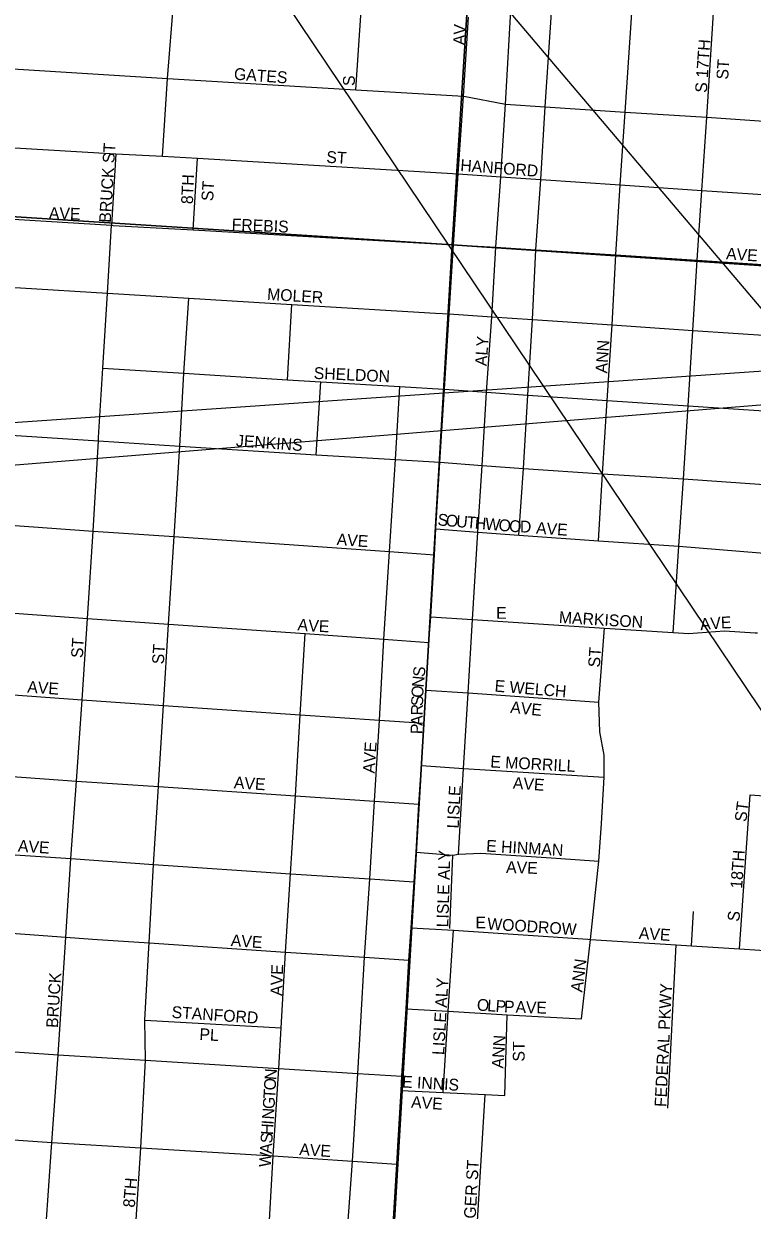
# Model space of a CAD drawing. Extents: x 0 to 34, y -6.2 to 22.
# Drawn here: x 7.214 to 7.798, y 15.431 to 16.383 of the extents above; entities that cross this region are included whole.
import ezdxf

# ---------------------------------------------------------------- set-up
doc = ezdxf.new("R2010")
doc.units = 0
for name, color, linetype in [('GM_X_City_Street', 7, 'Continuous'), ('GM_X_City_Street_Text', 7, 'Continuous'), ('GM_X_Corporation', 7, 'Continuous'), ('GM_X_Section', 7, 'Continuous'), ('SH_Data', 7, 'Continuous')]:
    doc.layers.add(name, color=color, linetype=linetype)

msp = doc.modelspace()

# ---------------------------------------------------------------- linework, layer by layer
at = {"layer": 'GM_X_City_Street'}
for points in [[(7.32508, 16.27676), (7.32919, 16.33906), (7.33421, 16.40232), (7.3364, 16.43316), (7.33992, 16.48027), (7.34271, 16.51996), (7.34542, 16.55929), (7.3485, 16.59888), (7.3519, 16.63865), (7.35476, 16.6813), (7.35765, 16.72304), (7.36053, 16.76297), (7.36453, 16.82192), (7.37158, 16.92099), (7.37633, 16.98634), (7.37905, 17.0267)], [(7.48036, 16.32986), (7.48466, 16.39349), (7.48699, 16.42288), (7.49064, 16.4691), (7.49371, 16.50912), (7.49674, 16.54846), (7.49957, 16.5877), (7.50258, 16.62725), (7.50564, 16.67008), (7.50871, 16.71187)], [(7.56258, 15.71668), (7.56656, 15.78555), (7.57032, 15.84609), (7.57386, 15.90499), (7.57829, 15.97507), (7.58172, 16.02856), (7.58521, 16.0873), (7.5894, 16.14776), (7.59258, 16.20355), (7.5967, 16.26005), (7.60038, 16.3184), (7.605, 16.39804), (7.6093, 16.4607), (7.61453, 16.53898)], [(7.61106, 15.9727), (7.6147, 16.02623), (7.61841, 16.08493), (7.62216, 16.14554), (7.62473, 16.20157), (7.62879, 16.25804), (7.63212, 16.31623), (7.63746, 16.396), (7.64133, 16.45859), (7.64678, 16.53671)], [(7.67496, 15.96812), (7.67822, 16.02195), (7.68186, 16.08073), (7.68587, 16.1413), (7.6889, 16.1974), (7.69243, 16.25376), (7.6964, 16.31198), (7.7017, 16.39152), (7.70564, 16.45429), (7.70723, 16.47221)], [(7.73492, 15.89456), (7.73958, 15.96384), (7.74334, 16.01793), (7.74708, 16.07645), (7.75068, 16.13694), (7.75424, 16.19312), (7.75796, 16.24906), (7.7619, 16.30801), (7.76695, 16.38727), (7.77087, 16.4499)], [(7.50892, 15.3982), (7.51307, 15.46819), (7.51391, 15.48255), (7.51655, 15.52729), (7.51727, 15.5388), (7.52053, 15.59278), (7.52292, 15.63183), (7.52454, 15.65774), (7.52697, 15.6946), (7.52856, 15.71838), (7.53091, 15.75694), (7.53286, 15.78789), (7.53508, 15.82183), (7.53654, 15.84839), (7.53887, 15.88668), (7.54041, 15.90725), (7.54328, 15.957), (7.54453, 15.97769), (7.5478, 16.03115), (7.55148, 16.08967), (7.55512, 16.15009), (7.5586, 16.20564), (7.56239, 16.26247), (7.56659, 16.3249), (7.57064, 16.38816)], [(7.07741, 16.35438), (7.17913, 16.34842), (7.32919, 16.33906), (7.48036, 16.32986), (7.56659, 16.3249), (7.56704, 16.32482)], [(7.56704, 16.32482), (7.60038, 16.3184), (7.63212, 16.31623), (7.6964, 16.31198), (7.7619, 16.30801), (7.82705, 16.30342), (7.91771, 16.29734), (7.99602, 16.29229), (8.02051, 16.29083)], [(6.89845, 16.30244), (6.94232, 16.29983), (6.9475, 16.29952), (6.97739, 16.29774), (7.07087, 16.29179), (7.08667, 16.29088), (7.17478, 16.28531), (7.28777, 16.2785), (7.32508, 16.27676), (7.35307, 16.27505), (7.56239, 16.26247)], [(7.28777, 16.2785), (7.28428, 16.22123), (7.28563, 16.22115)], [(7.34977, 16.21751), (7.35307, 16.27505)], [(7.56239, 16.26247), (7.5967, 16.26005), (7.62879, 16.25804), (7.69243, 16.25376), (7.75796, 16.24906), (7.82345, 16.24479), (7.91708, 16.23865), (7.99262, 16.23384), (8.01778, 16.23191)], [(6.97368, 16.24118), (7.08311, 16.23357), (7.28428, 16.22123)], [(7.27387, 16.05096), (7.27723, 16.10668), (7.28106, 16.16679), (7.28428, 16.22123)], [(7.28563, 16.22115), (7.34977, 16.21751), (7.46087, 16.21107), (7.46154, 16.21104)], [(7.46154, 16.21104), (7.5586, 16.20564), (7.55928, 16.20559)], [(7.55928, 16.20559), (7.59258, 16.20355), (7.62473, 16.20157), (7.6889, 16.1974), (7.75424, 16.19312), (7.8189, 16.18903), (7.88242, 16.18456), (7.91372, 16.18255), (7.98951, 16.17755), (8.07671, 16.17149), (8.14534, 16.16706)], [(7.15346, 16.17462), (7.21106, 16.17115), (7.28106, 16.16679), (7.34629, 16.16274), (7.42896, 16.15757), (7.54425, 16.15074)], [(7.32555, 15.8321), (7.3258, 15.83615), (7.32981, 15.90134), (7.33447, 15.97157), (7.3389, 16.04403), (7.34235, 16.10255), (7.34629, 16.16274)], [(7.42555, 16.09732), (7.42896, 16.15757)], [(7.54425, 16.15074), (7.55512, 16.15009), (7.5894, 16.14776), (7.62216, 16.14554), (7.68587, 16.1413), (7.75068, 16.13694), (7.8155, 16.13266), (7.87947, 16.12842), (7.94636, 16.12399)], [(7.27723, 16.10668), (7.34235, 16.10255), (7.42555, 16.09732), (7.45209, 16.09562), (7.5157, 16.09181), (7.5507, 16.08972)], [(7.44848, 16.03717), (7.45209, 16.09562)], [(7.48418, 15.5822), (7.48716, 15.63411), (7.49148, 15.69691), (7.49514, 15.75937), (7.49924, 15.82422), (7.50286, 15.88927), (7.50721, 15.95967), (7.51207, 16.03337), (7.5157, 16.09181)], [(7.5507, 16.08972), (7.55148, 16.08967), (7.58521, 16.0873), (7.61841, 16.08493), (7.68186, 16.08073), (7.74708, 16.07645), (7.81163, 16.07206), (7.87595, 16.06782), (7.94137, 16.06369)], [(6.90406, 16.07177), (6.93938, 16.06957), (6.96568, 16.06778), (7.00456, 16.06526), (7.07447, 16.06077), (7.13663, 16.05687), (7.20353, 16.05283), (7.27372, 16.04839), (7.3389, 16.04403), (7.44848, 16.03717), (7.51207, 16.03337), (7.5478, 16.03115), (7.58172, 16.02856), (7.6147, 16.02623), (7.67822, 16.02195), (7.74334, 16.01793), (7.80803, 16.01342), (7.87231, 16.0091), (7.93258, 16.00514)], [(7.22386, 15.29002), (7.22538, 15.31483), (7.22856, 15.36547), (7.23159, 15.41589), (7.23629, 15.48566), (7.24137, 15.55596), (7.2475, 15.65017), (7.25167, 15.71327), (7.25603, 15.77536), (7.26068, 15.84062), (7.26489, 15.90585), (7.26935, 15.97592), (7.27372, 16.04839), (7.27387, 16.05096)], [(7.06808, 15.9894), (7.07019, 15.98926), (7.19928, 15.98085), (7.26935, 15.97592), (7.33447, 15.97157), (7.50721, 15.95967), (7.54328, 15.957)], [(7.54453, 15.97769), (7.57829, 15.97507), (7.61106, 15.9727), (7.67496, 15.96812), (7.73958, 15.96384), (7.80485, 15.95861), (7.86883, 15.95433), (7.93546, 15.95041)], [(6.90834, 15.93074), (6.99731, 15.92399), (7.06587, 15.91941), (7.19508, 15.91077), (7.26489, 15.90585), (7.32981, 15.90134), (7.43951, 15.89384), (7.50286, 15.88927), (7.53887, 15.88668)], [(7.54041, 15.90725), (7.57386, 15.90499), (7.67974, 15.89804)], [(7.40989, 15.40452), (7.41398, 15.47475), (7.41856, 15.5449), (7.42034, 15.5774), (7.42379, 15.63819), (7.42779, 15.70103), (7.43178, 15.76365), (7.43572, 15.82856), (7.43951, 15.89384)], [(7.66146, 15.58475), (7.66868, 15.64846), (7.67539, 15.71125), (7.67742, 15.74127), (7.6795, 15.77854), (7.67957, 15.79608), (7.67615, 15.81501), (7.67519, 15.83884), (7.67974, 15.89804)], [(7.67974, 15.89804), (7.73492, 15.89456), (7.74727, 15.89369), (7.77621, 15.896), (7.78843, 15.89516), (7.80064, 15.89433), (7.80264, 15.89421)], [(7.06188, 15.8546), (7.19061, 15.84555), (7.26068, 15.84062), (7.3258, 15.83615), (7.43572, 15.82856), (7.49924, 15.82422), (7.53508, 15.82183)], [(7.53654, 15.84839), (7.57032, 15.84609), (7.67519, 15.83884)], [(7.32184, 15.772), (7.32555, 15.8321)], [(6.91246, 15.79876), (6.95277, 15.79636), (6.98898, 15.79399), (7.02417, 15.79172), (7.05739, 15.78945), (7.18602, 15.78035), (7.25603, 15.77536), (7.32178, 15.77107), (7.43178, 15.76365), (7.49514, 15.75937), (7.53091, 15.75694)], [(7.53286, 15.78789), (7.56656, 15.78555), (7.6795, 15.77854)], [(7.31417, 15.64176), (7.3144, 15.64569), (7.31775, 15.70853), (7.32178, 15.77107), (7.32184, 15.772)], [(7.78826, 15.641), (7.79685, 15.76448)], [(7.79685, 15.76448), (7.85678, 15.76018), (7.92659, 15.7549)], [(7.05319, 15.72691), (7.18218, 15.71782), (7.25167, 15.71327), (7.31775, 15.70853), (7.42779, 15.70103), (7.49148, 15.69691), (7.52697, 15.6946)], [(7.52856, 15.71838), (7.55803, 15.71611), (7.56258, 15.71668), (7.58051, 15.71749), (7.64109, 15.71365), (7.67539, 15.71125)], [(7.55563, 15.65705), (7.55803, 15.71611)], [(7.03816, 15.66529), (7.04925, 15.66448), (7.09295, 15.6614), (7.12955, 15.65876), (7.17765, 15.65543), (7.1819, 15.65505), (7.2475, 15.65017), (7.26883, 15.64867), (7.3144, 15.64569), (7.42379, 15.63819), (7.48716, 15.63411), (7.52292, 15.63183)], [(7.74968, 15.64338), (7.7512, 15.67083)], [(7.52454, 15.65774), (7.55858, 15.65588), (7.66654, 15.6486)], [(7.55417, 15.58577), (7.55449, 15.59079), (7.55858, 15.65588)], [(7.66654, 15.6486), (7.66868, 15.64846), (7.73741, 15.64414), (7.74968, 15.64338), (7.78826, 15.641)], [(7.31138, 15.55154), (7.31138, 15.55161), (7.31086, 15.58363), (7.31417, 15.64176)], [(7.7307, 15.51295), (7.73741, 15.64414)], [(7.78826, 15.641), (7.9186, 15.63221), (8.1509, 15.61549), (8.18538, 15.61304)], [(7.52053, 15.59278), (7.55449, 15.59079), (7.60174, 15.58781), (7.66146, 15.58475)], [(7.31086, 15.58363), (7.42034, 15.5774)], [(7.47882, 15.49225), (7.48182, 15.541), (7.48418, 15.5822)], [(7.5504, 15.52568), (7.55417, 15.58577)], [(7.59992, 15.52312), (7.60174, 15.58781)], [(7.03952, 15.56918), (7.04242, 15.56899), (7.08648, 15.56592), (7.12337, 15.56372), (7.13288, 15.56319), (7.17602, 15.56039), (7.18292, 15.55994), (7.24137, 15.55596), (7.31138, 15.55161), (7.41856, 15.5449), (7.48182, 15.541), (7.51727, 15.5388)], [(7.30314, 15.41128), (7.30775, 15.48128), (7.31138, 15.55154)], [(7.51655, 15.52729), (7.5504, 15.52568), (7.58413, 15.52403), (7.59992, 15.52312)], [(7.57553, 15.38297), (7.58413, 15.52403)], [(6.92201, 15.50623), (7.03803, 15.4985), (7.07853, 15.49607), (7.12826, 15.49289), (7.1786, 15.48944), (7.23629, 15.48566), (7.30775, 15.48128), (7.41398, 15.47475), (7.47748, 15.47054), (7.51307, 15.46819)], [(7.4622, 15.24253), (7.46686, 15.29897), (7.47241, 15.40068), (7.47748, 15.47054), (7.47882, 15.49225)]]:
    msp.add_lwpolyline(points, dxfattribs=at)
at = {"layer": 'GM_X_Corporation'}
msp.add_lwpolyline([(4.67978, 15.82571), (10.08962, 16.26123), (4.96941, 15.90904), (5.06729, 15.90337), (5.0717, 15.86574), (5.08067, 15.8658), (5.08009, 15.81885), (5.09901, 15.81981), (5.10092, 15.78197), (5.11984, 15.78293), (5.12271, 15.72617), (4.71157, 15.70531)], dxfattribs=at)
at = {"layer": 'GM_X_Section'}
msp.add_lwpolyline([(6.6036, 17.30139), (7.62278, 17.23025), (7.55762, 16.2055), (6.69487, 16.2608), (6.69615, 16.47781), (6.69681, 16.58979), (6.67582, 16.60734), (6.66866, 16.61383), (6.66566, 16.61915), (6.66266, 16.62447), (6.66079, 16.62789), (6.65777, 16.63056), (6.65098, 16.63439), (6.63588, 16.64282), (6.61965, 16.65201)], dxfattribs=at)
for points in [[(8.1365, 17.19384), (8.06985, 16.17099), (7.55762, 16.2055), (7.62278, 17.23025)], [(7.55762, 16.2055), (7.49702, 15.18339), (6.50864, 15.24579), (6.56582, 16.03526), (6.57042, 16.04432), (6.57346, 16.04657), (6.5731, 16.04961), (6.56933, 16.05266), (6.56368, 16.05648), (6.56029, 16.05991), (6.56031, 16.0637), (6.56223, 16.0671), (6.56757, 16.07351), (6.58204, 16.08629), (6.59348, 16.09759), (6.61215, 16.1149), (6.63197, 16.13523), (6.64151, 16.14654), (6.65068, 16.15898), (6.65796, 16.1722), (6.67103, 16.20394), (6.68525, 16.23642), (6.69481, 16.25), (6.69487, 16.2608)], [(7.55762, 16.2055), (8.06985, 16.17099), (8.00454, 15.15268), (7.49702, 15.18339)]]:
    msp.add_lwpolyline(points, close=True, dxfattribs=at)
at = {"layer": 'SH_Data'}
msp.add_lwpolyline([(9.8345, 13.7654), (6.76179, 17.38412), (9.8345, 12.81564)], close=True, dxfattribs=at)

# ---------------------------------------------------------------- texts
at = {"layer": 'GM_X_City_Street_Text'}
for s, height, rotation, p in [('V', 0.00947, 87.37659, (7.56817, 16.37382)), ('A', 0.00947, 87.37659, (7.56779, 16.3655)), ('S 17TH', 0.00947, 86.10186, (7.76196, 16.32724)), ('ST', 0.00947, 86.42621, (7.77905, 16.33788)), ('GATES', 0.00947, 355.83871, (7.3822, 16.33806)), ('S', 0.00947, 90, (7.47946, 16.33295)), ('BRUCK ST', 0.00947, 86.63221, (7.28362, 16.22306)), ('ST', 0.00947, 356.41176, (7.45635, 16.2714)), ('HANFORD', 0.00947, 355.73453, (7.56387, 16.26473)), ('8TH', 0.00947, 87.71078, (7.34946, 16.23802)), ('ST', 0.00947, 86.42535, (7.36572, 16.24038)), ('AVE', 0.00947, 358.02636, (7.2338, 16.2264)), ('FREBIS', 0.00947, 357.56473, (7.38048, 16.21723)), ('AVE', 0.00947, 356.0574, (7.77719, 16.1939)), ('MOLER', 0.00947, 356.49393, (7.40885, 16.1614)), ('ALY', 0.00947, 86.05688, (7.58529, 16.10808)), ('ANN', 0.00947, 86.18059, (7.68196, 16.10224)), ('SHELDON', 0.00947, 357.35565, (7.44632, 16.09807)), ('JENKINS', 0.00947, 355.9166, (7.38386, 16.0439)), ('S', 0.00947, 354.96635, (7.54556, 15.98056)), ('O', 0.00947, 354.9441, (7.5522, 15.97998)), ('U', 0.00947, 354.96972, (7.56051, 15.97925)), ('T', 0.00947, 354.93914, (7.5688, 15.97851)), ('H', 0.00947, 354.95913, (7.57545, 15.97793)), ('W', 0.00947, 354.96603, (7.58376, 15.97719)), ('O', 0.00947, 354.9441, (7.59454, 15.97624)), ('O', 0.00947, 355.70229, (7.60298, 15.9755)), ('D', 0.00947, 359.27204, (7.61193, 15.97484)), ('AVE', 0.00947, 356.05688, (7.62469, 15.9739)), ('AVE', 0.00947, 356.0499, (7.46469, 15.96474)), ('E', 0.00947, 0.00001, (7.59291, 15.90556)), ('A', 0.00947, 354.33072, (7.43319, 15.89638)), ('V', 0.00947, 356.97557, (7.44196, 15.89553)), ('E', 0.00947, 357.40233, (7.45036, 15.89508)), ('MARKISON', 0.00947, 356.59155, (7.64305, 15.90223)), ('A', 0.00947, 4.74912, (7.75691, 15.8964)), ('V', 0.00947, 4.72553, (7.76521, 15.89709)), ('E', 0.00947, 2.37798, (7.77341, 15.89777)), ('ST', 0.00947, 86.42535, (7.26112, 15.8739)), ('ST', 0.00947, 86.42621, (7.32613, 15.8689)), ('ST', 0.00947, 86.42535, (7.67613, 15.8664)), ('S', 0.00947, 84.30843, (7.53543, 15.85859)), ('AVE', 0.00947, 356.0574, (7.21636, 15.8464)), ('N', 0.00947, 84.74618, (7.53467, 15.85031)), ('E WELCH', 0.00947, 355.31673, (7.59138, 15.84723)), ('O', 0.00947, 87.50759, (7.53431, 15.84211)), ('R', 0.00947, 88.64011, (7.53398, 15.82799)), ('S', 0.00947, 88.63411, (7.53416, 15.83549)), ('AVE', 0.00947, 354.09695, (7.60391, 15.83019)), ('A', 0.00947, 88.64164, (7.53378, 15.81966)), ('P', 0.00947, 88.63411, (7.53362, 15.81299)), ('AVE', 0.00947, 86.05688, (7.49529, 15.78141)), ('E MORRILL', 0.00947, 356.90459, (7.588, 15.7864)), ('AVE', 0.00947, 356.05688, (7.38219, 15.76973)), ('LISLE', 0.00947, 86.98872, (7.56279, 15.73722)), ('AVE', 0.00947, 356.04938, (7.60607, 15.76931)), ('ST', 0.00947, 82.88002, (7.79364, 15.74234)), ('AVE', 0.00947, 356.05688, (7.20886, 15.7189)), ('E HINMAN', 0.00947, 356.63222, (7.58467, 15.7189)), ('LISLE ALY', 0.00947, 88.3643, (7.55446, 15.658)), ('18TH', 0.00947, 85.9166, (7.79029, 15.68891)), ('AVE', 0.00947, 358.0261, (7.60074, 15.70179)), ('E', 0.00947, 0.00001, (7.57624, 15.65723)), ('WOODROW', 0.00947, 356.23804, (7.58552, 15.6564)), ('S', 0.00947, 82.87834, (7.7878, 15.66234)), ('AVE', 0.00947, 356.05688, (7.70719, 15.6489)), ('AVE', 0.00947, 356.05688, (7.3797, 15.64307)), ('AVE', 0.00947, 88.02635, (7.42112, 15.60301)), ('ANN', 0.00947, 82.40916, (7.66197, 15.60569)), ('BRUCK', 0.00947, 86.42564, (7.24112, 15.57723)), ('LISLE ALY', 0.00947, 86.73074, (7.55112, 15.55551)), ('FEDERAL PKWY', 0.0094697, 87.32395, (7.72945, 15.51387)), ('O', 0.00947, 356.21645, (7.57719, 15.5914)), ('L', 0.00947, 356.24105, (7.58551, 15.59085)), ('P', 0.00947, 356.22772, (7.59217, 15.59041)), ('P', 0.00947, 357.32783, (7.59902, 15.58996)), ('A', 0.00947, 358.37144, (7.60836, 15.58957)), ('V', 0.00947, 358.40519, (7.6167, 15.58933)), ('E', 0.00947, 358.41145, (7.62503, 15.5891)), ('STANFORD', 0.00947, 356.08102, (7.33219, 15.58557)), ('PL', 0.00947, 356.42622, (7.35451, 15.56782)), ('ANN', 0.00947, 86.18833, (7.59863, 15.54474)), ('ST', 0.00947, 90, (7.61575, 15.55045)), ('N', 0.00947, 86.12775, (7.41638, 15.53542)), ('O', 0.00947, 86.36912, (7.41585, 15.52711)), ('E INNIS', 0.00947, 356.49837, (7.51718, 15.52973)), ('T', 0.00947, 86.39127, (7.41543, 15.52046)), ('AVE', 0.00947, 356.05688, (7.52441, 15.51348)), ('N', 0.00947, 86.36732, (7.41438, 15.50383)), ('G', 0.00947, 86.38982, (7.41491, 15.51215)), ('H', 0.00947, 86.38982, (7.41359, 15.49135)), ('I', 0.00947, 86.36912, (7.41412, 15.49967)), ('A', 0.00947, 86.36912, (7.41265, 15.47638)), ('S', 0.00947, 86.39326, (7.41317, 15.4847)), ('AVE', 0.00947, 356.05688, (7.43469, 15.47557)), ('W', 0.00947, 86.38275, (7.41196, 15.46557)), ('WAGER ST', 0.00947, 86.7772, (7.57529, 15.40389)), ('8TH', 0.00947, 85.42885, (7.3028, 15.4331))]:
    msp.add_text(s, height=height, rotation=rotation, dxfattribs=at).set_placement(p)

doc.saveas('drawing.dxf')
